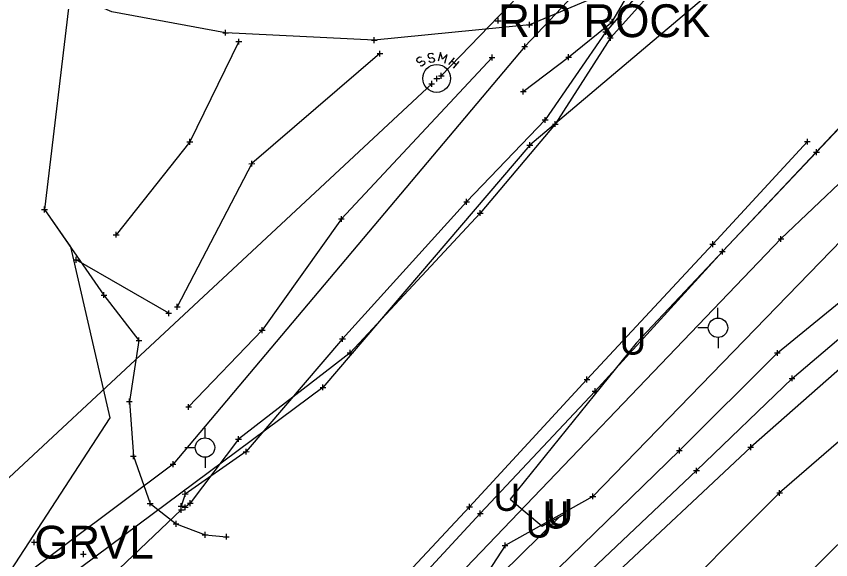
# Model space of a CAD drawing. Extents: x -1 to 1157254, y -1 to 2021979.
# Drawn here: x 1149359.7 to 1149538.4, y 2018913.3 to 2019032.4 of the extents above; entities that cross this region are included whole.
import ezdxf

# ---------------------------------------------------------------- set-up
doc = ezdxf.new("R2010")
doc.units = 0
for name, color, linetype in [('S_BUILDING_ANNOT', 7, 'Continuous'), ('S_CAL_CORNER_ANNOT', 7, 'Continuous'), ('S_CATCH_BASIN', 7, 'Continuous'), ('S_CONTOUR_ANNOT', 7, 'Continuous'), ('S_CONTOUR_MAJOR', 7, 'Continuous'), ('S_CONTOUR_MINOR', 7, 'Continuous'), ('S_CTL_TABLE', 7, 'Continuous'), ('S_DRIVEWAY_ANNOT', 7, 'Continuous'), ('S_DROP_INLET', 7, 'Continuous'), ('S_DROP_INLET_ANNOT', 7, 'Continuous'), ('S_DTM_PAVEMENT', 7, 'Continuous'), ('S_EDGE_BITUMINOUS_ANNOT', 7, 'Continuous'), ('S_EDGE_CONCRETE', 7, 'Continuous'), ('S_EDGE_PAVEMENT_ANNOT', 7, 'Continuous'), ('S_ENV_CONSTRAINT', 7, 'Continuous'), ('S_EXIST_ROW_ANNOT', 7, 'Continuous'), ('S_FENCE', 7, 'Continuous'), ('S_FLAG_POLE', 7, 'Continuous'), ('S_GAS_PUMP_ISLAND_ANNOT', 7, 'Continuous'), ('S_GATE', 7, 'Continuous')]:
    doc.layers.add(name, color=color, linetype=linetype)

msp = doc.modelspace()

# ---------------------------------------------------------------- linework, layer by layer
at = {"layer": 'S_BUILDING_ANNOT'}
for p, q in [((1149465.44, 2019030.78), (1149465.44, 2019032.05)), ((1149464.8, 2019031.42), (1149466.07, 2019031.42)), ((1149465.44, 2019031.42), (1149465.44, 2019031.42)), ((1149488.43, 2019028.95), (1149489.71, 2019028.95)), ((1149489.07, 2019028.31), (1149489.07, 2019029.58)), ((1149489.07, 2019028.95), (1149489.07, 2019028.95)), ((1149490.07, 2019027.02), (1149490.06, 2019028.29)), ((1149489.43, 2019027.65), (1149490.7, 2019027.66)), ((1149490.07, 2019027.66), (1149490.07, 2019027.66)), ((1149470.61, 2019025.77), (1149471.89, 2019025.78)), ((1149471.25, 2019025.14), (1149471.25, 2019026.41)), ((1149471.25, 2019025.78), (1149471.25, 2019025.78)), ((1149451.99, 2019018.1), (1149451.99, 2019019.37)), ((1149452.32, 2019019.35), (1149453.59, 2019019.35)), ((1149452.96, 2019018.71), (1149452.95, 2019019.98)), ((1149452.95, 2019019.35), (1149452.95, 2019019.35)), ((1149450.21, 2019017.6), (1149451.49, 2019017.6)), ((1149450.85, 2019016.96), (1149450.85, 2019018.23)), ((1149450.85, 2019017.6), (1149450.85, 2019017.6)), ((1149451.35, 2019018.73), (1149452.63, 2019018.74)), ((1149451.99, 2019018.73), (1149451.99, 2019018.73)), ((1149475.1, 2019009.67), (1149476.38, 2019009.67)), ((1149475.74, 2019009.04), (1149475.74, 2019010.31)), ((1149475.74, 2019009.67), (1149475.74, 2019009.67)), ((1149477.32, 2019008.76), (1149478.59, 2019008.76)), ((1149477.96, 2019008.13), (1149477.96, 2019009.4)), ((1149477.96, 2019008.76), (1149477.96, 2019008.76)), ((1149533.26, 2019004.27), (1149533.26, 2019005.55)), ((1149471.76, 2019004.16), (1149473.04, 2019004.16)), ((1149472.4, 2019003.52), (1149472.4, 2019004.79)), ((1149472.4, 2019004.16), (1149472.4, 2019004.16)), ((1149532.62, 2019004.91), (1149533.9, 2019004.91)), ((1149533.26, 2019004.91), (1149533.26, 2019004.91)), ((1149535.26, 2019001.98), (1149535.26, 2019003.25)), ((1149534.62, 2019002.62), (1149535.9, 2019002.62)), ((1149535.26, 2019002.62), (1149535.26, 2019002.62)), ((1149457.88, 2018991.72), (1149459.15, 2018991.72)), ((1149458.51, 2018991.09), (1149458.51, 2018992.36)), ((1149458.51, 2018991.72), (1149458.51, 2018991.72)), ((1149365.27, 2018990.03), (1149366.54, 2018990.03)), ((1149365.91, 2018989.4), (1149365.9, 2018990.67)), ((1149365.9, 2018990.03), (1149365.9, 2018990.03)), ((1149460.84, 2018989.26), (1149462.11, 2018989.26)), ((1149461.47, 2018988.63), (1149461.47, 2018989.9)), ((1149461.47, 2018989.26), (1149461.47, 2018989.26)), ((1149526.83, 2018983.58), (1149528.1, 2018983.58)), ((1149527.46, 2018982.94), (1149527.46, 2018984.21)), ((1149527.46, 2018983.58), (1149527.46, 2018983.58)), ((1149511.87, 2018982.43), (1149513.14, 2018982.43)), ((1149512.51, 2018981.79), (1149512.5, 2018983.06)), ((1149512.51, 2018982.43), (1149512.51, 2018982.43)), ((1149514, 2018980.81), (1149515.27, 2018980.81)), ((1149514.64, 2018980.17), (1149514.64, 2018981.44)), ((1149514.64, 2018980.81), (1149514.64, 2018980.81)), ((1149372.24, 2018979), (1149373.51, 2018979)), ((1149372.88, 2018978.37), (1149372.88, 2018979.64)), ((1149372.88, 2018979), (1149372.88, 2018979)), ((1149378.32, 2018971.27), (1149379.6, 2018971.28)), ((1149378.96, 2018970.64), (1149378.96, 2018971.91)), ((1149378.96, 2018971.28), (1149378.96, 2018971.28)), ((1149393.17, 2018966.66), (1149393.16, 2018967.93)), ((1149392.53, 2018967.3), (1149393.8, 2018967.3)), ((1149393.17, 2018967.3), (1149393.17, 2018967.3)), ((1149431.28, 2018961.02), (1149431.27, 2018962.29)), ((1149386, 2018961.34), (1149387.27, 2018961.34)), ((1149386, 2018961.33), (1149387.27, 2018961.34)), ((1149386.63, 2018960.7), (1149386.63, 2018961.97)), ((1149386.63, 2018961.33), (1149386.63, 2018961.33)), ((1149386.64, 2018960.71), (1149386.64, 2018961.98)), ((1149386.64, 2018961.34), (1149386.64, 2018961.34)), ((1149430.64, 2018961.65), (1149431.91, 2018961.65)), ((1149431.27, 2018961.65), (1149431.27, 2018961.65)), ((1149432.33, 2018958.61), (1149433.6, 2018958.61)), ((1149432.96, 2018957.97), (1149432.96, 2018959.24)), ((1149432.96, 2018958.61), (1149432.96, 2018958.61)), ((1149526.05, 2018958.59), (1149527.32, 2018958.59)), ((1149526.69, 2018957.95), (1149526.68, 2018959.22)), ((1149526.69, 2018958.59), (1149526.69, 2018958.59)), ((1149484.91, 2018952.13), (1149484.91, 2018953.4)), ((1149529.9, 2018952.37), (1149529.9, 2018953.65)), ((1149427, 2018950.4), (1149426.99, 2018951.67)), ((1149484.28, 2018952.77), (1149485.55, 2018952.77)), ((1149484.91, 2018952.77), (1149484.91, 2018952.77)), ((1149529.26, 2018953.01), (1149530.54, 2018953.01)), ((1149529.9, 2018953.01), (1149529.9, 2018953.01)), ((1149426.36, 2018951.03), (1149427.63, 2018951.04)), ((1149427, 2018951.04), (1149427, 2018951.04)), ((1149486.08, 2018950.24), (1149487.35, 2018950.24)), ((1149486.72, 2018949.6), (1149486.71, 2018950.87)), ((1149486.72, 2018950.24), (1149486.72, 2018950.24)), ((1149383.91, 2018947.96), (1149385.18, 2018947.96)), ((1149384.55, 2018947.32), (1149384.55, 2018948.59)), ((1149384.55, 2018947.96), (1149384.55, 2018947.96)), ((1149407.84, 2018939.71), (1149409.11, 2018939.72)), ((1149408.48, 2018939.08), (1149408.48, 2018940.35)), ((1149408.48, 2018939.72), (1149408.48, 2018939.72)), ((1149410.16, 2018936.32), (1149410.16, 2018937.59)), ((1149504.55, 2018937.2), (1149505.83, 2018937.2)), ((1149505.19, 2018936.56), (1149505.19, 2018937.83)), ((1149505.19, 2018937.2), (1149505.19, 2018937.2)), ((1149384.78, 2018935.98), (1149386.05, 2018935.98)), ((1149385.42, 2018935.34), (1149385.41, 2018936.61)), ((1149385.41, 2018935.98), (1149385.41, 2018935.98)), ((1149409.52, 2018936.95), (1149410.8, 2018936.96)), ((1149410.16, 2018936.96), (1149410.16, 2018936.96)), ((1149393.48, 2018934.21), (1149394.75, 2018934.21)), ((1149394.11, 2018933.57), (1149394.11, 2018934.85)), ((1149394.11, 2018934.21), (1149394.11, 2018934.21)), ((1149508.31, 2018932.79), (1149509.59, 2018932.79)), ((1149508.95, 2018932.16), (1149508.95, 2018933.43)), ((1149508.95, 2018932.79), (1149508.95, 2018932.79)), ((1149396.78, 2018927.03), (1149396.77, 2018928.3)), ((1149396.14, 2018927.66), (1149397.41, 2018927.67)), ((1149396.78, 2018927.66), (1149396.78, 2018927.66)), ((1149485.57, 2018927.15), (1149486.84, 2018927.15)), ((1149486.21, 2018926.51), (1149486.21, 2018927.78)), ((1149486.21, 2018927.15), (1149486.21, 2018927.15)), ((1149388.47, 2018925.62), (1149389.74, 2018925.62)), ((1149389.11, 2018924.98), (1149389.11, 2018926.26)), ((1149389.11, 2018925.62), (1149389.11, 2018925.62)), ((1149395.25, 2018925.02), (1149396.52, 2018925.02)), ((1149395.88, 2018924.38), (1149395.88, 2018925.66)), ((1149395.88, 2018925.02), (1149395.88, 2018925.02)), ((1149395.92, 2018923.54), (1149395.92, 2018924.81)), ((1149396.13, 2018924.74), (1149397.4, 2018924.75)), ((1149396.76, 2018924.11), (1149396.76, 2018925.38)), ((1149396.76, 2018924.74), (1149396.76, 2018924.74)), ((1149397.25, 2018925.65), (1149398.52, 2018925.66)), ((1149397.88, 2018925.02), (1149397.88, 2018926.29)), ((1149397.88, 2018925.65), (1149397.88, 2018925.65)), ((1149458.49, 2018924.84), (1149459.77, 2018924.84)), ((1149459.13, 2018924.21), (1149459.13, 2018925.48)), ((1149459.13, 2018924.84), (1149459.13, 2018924.84)), ((1149395.28, 2018924.18), (1149396.56, 2018924.18)), ((1149395.92, 2018924.18), (1149395.92, 2018924.18)), ((1149460.87, 2018923.38), (1149462.14, 2018923.38)), ((1149461.51, 2018922.75), (1149461.51, 2018924.02)), ((1149461.51, 2018923.38), (1149461.51, 2018923.38)), ((1149394.13, 2018921.13), (1149395.41, 2018921.14)), ((1149394.77, 2018920.5), (1149394.77, 2018921.77)), ((1149394.77, 2018921.14), (1149394.77, 2018921.14)), ((1149401.15, 2018918.07), (1149401.15, 2018919.34)), ((1149363.67, 2018916.46), (1149363.67, 2018917.73)), ((1149400.51, 2018918.7), (1149401.78, 2018918.7)), ((1149401.15, 2018918.7), (1149401.15, 2018918.7)), ((1149405.18, 2018918.31), (1149406.45, 2018918.31)), ((1149405.82, 2018917.67), (1149405.81, 2018918.95)), ((1149405.81, 2018918.31), (1149405.81, 2018918.31)), ((1149363.03, 2018917.1), (1149364.31, 2018917.1)), ((1149363.67, 2018917.1), (1149363.67, 2018917.1)), ((1149466.32, 2018916.39), (1149467.59, 2018916.4)), ((1149466.96, 2018915.76), (1149466.96, 2018917.03)), ((1149466.96, 2018916.4), (1149466.96, 2018916.4)), ((1149373.81, 2018914.49), (1149375.08, 2018914.49)), ((1149374.45, 2018913.85), (1149374.44, 2018915.13)), ((1149374.44, 2018914.49), (1149374.44, 2018914.49))]:
    msp.add_line(p, q, dxfattribs=at)
at = {"layer": 'S_CAL_CORNER_ANNOT'}
msp.add_lwpolyline([(1150682.05, 2019865.85), (1150601.54, 2019813.47), (1150510.58, 2019743.97), (1150405.28, 2019665.92), (1150310.69, 2019593.56), (1150188.92, 2019499.64), (1150039.45, 2019388.15), (1149962.15, 2019331.17), (1149944.63, 2019319.08), (1149774.15, 2019191.52), (1149712.73, 2019145.6), (1149665.81, 2019108.74), (1149605.46, 2019057.66), (1149527.46, 2018983.58), (1149450.12, 2018902.93), (1149278.32, 2018738.82), (1149257.2, 2018716.38), (1149237.23, 2018691.25), (1149165.09, 2018617.77), (1149125.26, 2018579.57), (1149069.5, 2018523.84), (1149012.03, 2018473.77), (1148938.88, 2018408.55)], dxfattribs=at)
at = {"layer": 'S_CATCH_BASIN'}
for p, q in [((1149513.66, 2018966.22), (1149513.66, 2018968.47)), ((1149511.57, 2018964.09), (1149509.24, 2018964.09)), ((1149513.74, 2018959.67), (1149513.74, 2018962)), ((1149401.13, 2018939.95), (1149401.13, 2018942.2)), ((1149399.03, 2018937.82), (1149396.71, 2018937.82)), ((1149401.2, 2018933.41), (1149401.2, 2018935.73))]:
    msp.add_line(p, q, dxfattribs=at)
for centre in [(1149513.66, 2018964.11), (1149401.13, 2018937.84)]:
    msp.add_circle(centre, 2.13, dxfattribs=at)
at = {"layer": 'S_CONTOUR_ANNOT'}
for points in [[(1149931.59, 2019393.98), (1149688.42, 2019230.92), (1149605.65, 2019167.39), (1149471.25, 2019025.78), (1149394.11, 2018934.21), (1149347.84, 2018899.68), (1149226.01, 2018779.47), (1149177.83, 2018729.86), (1148942.89, 2018495.75), (1148824.88, 2018414.4), (1148656.17, 2018321.62), (1148428.99, 2018204.95), (1148398.58, 2018185.48), (1148319.88, 2018123.12), (1148171.01, 2018007.64), (1148133.82, 2017978.13)], [(1149934.92, 2019374.11), (1149784.56, 2019258.12), (1149678.43, 2019178.13), (1149472.4, 2019004.16), (1149427, 2018951.04), (1149358.36, 2018900), (1149291.74, 2018823.41), (1149233.45, 2018767.69), (1149177.23, 2018710.91), (1149078.39, 2018616.37), (1148964.19, 2018499.8), (1148972, 2018491.15), (1148988.16, 2018467.17), (1149002.28, 2018452.45)]]:
    msp.add_lwpolyline(points, dxfattribs=at)
at = {"layer": 'S_CONTOUR_MINOR'}
for p, q in [((1149447.63, 2019023.07), (1149447.55, 2019022.68)), ((1149448.17, 2019023.45), (1149447.63, 2019023.07)), ((1149448.6, 2019023.38), (1149448.17, 2019023.45)), ((1149454.6, 2019021.83), (1149455.84, 2019023.3)), ((1149447.55, 2019022.68), (1149447.74, 2019022.41)), ((1149447.74, 2019022.41), (1149448.17, 2019022.29)), ((1149448.17, 2019022.29), (1149448.71, 2019022.64)), ((1149448.71, 2019021.48), (1149448.32, 2019021.56)), ((1149448.71, 2019022.64), (1149449.18, 2019022.56)), ((1149449.25, 2019021.87), (1149448.71, 2019021.48)), ((1149449.18, 2019022.56), (1149449.33, 2019022.29)), ((1149449.33, 2019022.29), (1149449.25, 2019021.87)), ((1149455.26, 2019022.6), (1149456.23, 2019021.79)), ((1149456.81, 2019022.49), (1149455.57, 2019021.01))]:
    msp.add_line(p, q, dxfattribs=at)
for points in [[(1149495.14, 2019063.02), (1149452.95, 2019019.35)], [(1149451.27, 2019024), (1149450.92, 2019024.27), (1149450.26, 2019024.19), (1149450.03, 2019023.84), (1149450.07, 2019023.53), (1149450.42, 2019023.22), (1149451.04, 2019023.34), (1149451.42, 2019023.03), (1149451.46, 2019022.72), (1149451.19, 2019022.33), (1149450.57, 2019022.25), (1149450.22, 2019022.52)], [(1149453.71, 2019022.14), (1149454.25, 2019024), (1149453.2, 2019022.99), (1149452.82, 2019024.42), (1149452.28, 2019022.56)], [(1149450.85, 2019017.6), (1149294.1, 2018871.71)]]:
    msp.add_lwpolyline(points, dxfattribs=at)
msp.add_circle((1149451.95, 2019018.77), 3.05, dxfattribs=at)
at = {"layer": 'S_CTL_TABLE'}
for p, q in [((1149490.47, 2019030.54), (1149490.47, 2019031.81)), ((1149471.7, 2019030.54), (1149472.97, 2019030.55)), ((1149472.34, 2019029.91), (1149472.33, 2019031.18)), ((1149472.33, 2019030.55), (1149472.33, 2019030.55)), ((1149489.84, 2019031.17), (1149491.11, 2019031.18)), ((1149490.47, 2019031.18), (1149490.47, 2019031.18)), ((1149405, 2019028.8), (1149406.27, 2019028.8)), ((1149405.64, 2019028.17), (1149405.63, 2019029.44)), ((1149405.64, 2019028.8), (1149405.64, 2019028.8)), ((1149407.91, 2019026.84), (1149409.18, 2019026.84)), ((1149408.55, 2019026.2), (1149408.54, 2019027.47)), ((1149408.55, 2019026.84), (1149408.55, 2019026.84)), ((1149437.62, 2019027.17), (1149438.89, 2019027.17)), ((1149438.25, 2019026.53), (1149438.25, 2019027.81)), ((1149438.25, 2019027.17), (1149438.25, 2019027.17)), ((1149439.5, 2019023.57), (1149439.5, 2019024.84)), ((1149438.86, 2019024.21), (1149440.14, 2019024.21)), ((1149439.5, 2019024.21), (1149439.5, 2019024.21)), ((1149463.47, 2019023.36), (1149464.74, 2019023.36)), ((1149464.11, 2019022.72), (1149464.1, 2019024)), ((1149464.1, 2019023.36), (1149464.1, 2019023.36)), ((1149480.26, 2019023.42), (1149481.53, 2019023.42)), ((1149480.9, 2019022.79), (1149480.9, 2019024.06)), ((1149480.9, 2019023.42), (1149480.9, 2019023.42)), ((1149470.31, 2019015.88), (1149471.58, 2019015.88)), ((1149470.95, 2019015.24), (1149470.95, 2019016.51)), ((1149470.95, 2019015.88), (1149470.95, 2019015.88)), ((1149397.78, 2019004.23), (1149397.78, 2019005.5)), ((1149397.14, 2019004.86), (1149398.42, 2019004.87)), ((1149397.78, 2019004.87), (1149397.78, 2019004.87)), ((1149410.77, 2019000.08), (1149412.05, 2019000.09)), ((1149411.41, 2018999.45), (1149411.41, 2019000.72)), ((1149411.41, 2019000.09), (1149411.41, 2019000.09)), ((1149430.41, 2018987.97), (1149431.68, 2018987.98)), ((1149431.05, 2018987.34), (1149431.05, 2018988.61)), ((1149431.05, 2018987.97), (1149431.05, 2018987.97)), ((1149380.99, 2018984.5), (1149382.26, 2018984.5)), ((1149381.62, 2018983.87), (1149381.62, 2018985.14)), ((1149381.62, 2018984.5), (1149381.62, 2018984.5)), ((1149395.05, 2018968.07), (1149395.04, 2018969.35)), ((1149394.41, 2018968.71), (1149395.68, 2018968.71)), ((1149395.04, 2018968.71), (1149395.04, 2018968.71)), ((1149413.67, 2018962.94), (1149413.66, 2018964.21)), ((1149413.03, 2018963.58), (1149414.3, 2018963.58)), ((1149413.66, 2018963.58), (1149413.66, 2018963.58)), ((1149396.89, 2018946.75), (1149398.16, 2018946.75)), ((1149397.53, 2018946.11), (1149397.52, 2018947.38)), ((1149397.52, 2018946.75), (1149397.52, 2018946.75)), ((1149520.19, 2018937.94), (1149521.47, 2018937.94)), ((1149520.83, 2018937.3), (1149520.83, 2018938.58)), ((1149520.83, 2018937.94), (1149520.83, 2018937.94)), ((1149527.18, 2018927.26), (1149527.17, 2018928.53)), ((1149526.54, 2018927.9), (1149527.81, 2018927.9)), ((1149527.17, 2018927.9), (1149527.17, 2018927.9))]:
    msp.add_line(p, q, dxfattribs=at)
at = {"layer": 'S_DRIVEWAY_ANNOT'}
for points in [[(1149497.48, 2019039.56), (1149496.43, 2019037.66), (1149489.07, 2019028.95), (1149475.74, 2019009.67), (1149458.51, 2018991.72), (1149431.27, 2018961.65), (1149410.16, 2018936.96), (1149396.78, 2018927.66), (1149395.88, 2018925.02)], [(1149499.26, 2019039.26), (1149498.04, 2019036.62), (1149490.07, 2019027.66), (1149477.96, 2019008.76), (1149461.47, 2018989.26), (1149432.96, 2018958.61), (1149408.48, 2018939.72), (1149397.88, 2018925.65), (1149396.76, 2018924.74)], [(1149376.61, 2018808.08), (1149378.14, 2018810.98), (1149389.01, 2018823.67), (1149409.46, 2018847.56), (1149440.18, 2018874.39), (1149475.97, 2018908.75), (1149505.19, 2018937.2), (1149526.69, 2018958.59), (1149556.52, 2018982.92), (1149580.72, 2019006.3), (1149603.46, 2019020.75), (1149621.36, 2019031.87)], [(1149376.44, 2018806.04), (1149380.49, 2018808.15), (1149394.25, 2018816.7), (1149415.4, 2018840.88), (1149444.35, 2018868.67), (1149479.15, 2018904.69), (1149508.95, 2018932.79), (1149529.9, 2018953.01), (1149559.1, 2018977.73), (1149584.9, 2019000.96), (1149605.2, 2019016.88), (1149625.32, 2019028.84)]]:
    msp.add_lwpolyline(points, dxfattribs=at)
at = {"layer": 'S_DROP_INLET'}
for points in [[(1149587.97, 2019053.68), (1149551.81, 2019020.22), (1149495.72, 2018960.76), (1149468.06, 2018926.51), (1149475.12, 2018920.64), (1149479.69, 2018923.12)], [(1149478.88, 2018922.64), (1149385.84, 2018831.36), (1149330.57, 2018775.16), (1149250.6, 2018696.8), (1149231.5, 2018678.75), (1149169.67, 2018614.3), (1149128.45, 2018577.04), (1149075.89, 2018529.44), (1149016.28, 2018476.33), (1148941.34, 2018408.7), (1148861.11, 2018354.7), (1148778.49, 2018311.96), (1148755.86, 2018297.95), (1148577.39, 2018201.52), (1148460.64, 2018136.54), (1148334.57, 2018041.74), (1148195.53, 2017935.77), (1148138.82, 2017892.99)]]:
    msp.add_lwpolyline(points, dxfattribs=at)
at = {"layer": 'S_DROP_INLET_ANNOT'}
msp.add_lwpolyline([(1149395.92, 2018924.18), (1149362.83, 2018892.8)], dxfattribs=at)
at = {"layer": 'S_DTM_PAVEMENT'}
msp.add_lwpolyline([(1149393.17, 2018967.3), (1149372.88, 2018979)], dxfattribs=at)
at = {"layer": 'S_EDGE_BITUMINOUS_ANNOT'}
for points in [[(1149470.95, 2019015.88), (1149480.9, 2019023.42), (1149490.47, 2019031.18), (1149495.83, 2019040.44), (1149472.33, 2019030.55), (1149438.25, 2019027.17), (1149405.64, 2019028.8), (1149380.72, 2019033.36), (1149343.09, 2019049.73), (1149326.07, 2019062), (1149301.59, 2019079.71), (1149283.88, 2019097.02), (1149282.36, 2019113.17), (1149265.52, 2019117.42)], [(1149408.55, 2019026.84), (1149397.78, 2019004.87), (1149381.62, 2018984.5)], [(1149439.5, 2019024.21), (1149411.41, 2019000.09), (1149395.04, 2018968.71)], [(1149464.1, 2019023.36), (1149431.05, 2018987.97), (1149413.66, 2018963.58), (1149397.52, 2018946.75)], [(1149660.03, 2018976.65), (1149631.99, 2018985.75), (1149603.08, 2018981.73), (1149578.25, 2018978.73), (1149548.87, 2018962.54), (1149520.83, 2018937.94), (1149489.35, 2018908.4), (1149463.06, 2018881.32), (1149437.76, 2018856.18), (1149412.61, 2018831.09), (1149389.75, 2018805.71)], [(1149658.16, 2018967.63), (1149629.1, 2018977.29), (1149605.68, 2018973.28), (1149580.28, 2018967.82), (1149554.15, 2018951.27), (1149527.17, 2018927.9), (1149498.99, 2018899.71), (1149468.02, 2018871.41), (1149443.75, 2018849.24), (1149417.05, 2018823.84), (1149394.92, 2018799.71)]]:
    msp.add_lwpolyline(points, dxfattribs=at)
at = {"layer": 'S_EDGE_CONCRETE'}
msp.add_lwpolyline([(1149391.91, 2018853), (1149412.71, 2018874.99), (1149434.25, 2018898.25), (1149459.13, 2018924.84), (1149484.91, 2018952.77), (1149512.51, 2018982.43), (1149533.26, 2019004.91)], dxfattribs=at)
at = {"layer": 'S_EDGE_PAVEMENT_ANNOT'}
msp.add_lwpolyline([(1149365.9, 2018990.03), (1149378.96, 2018971.28), (1149386.64, 2018961.34)], dxfattribs=at)
at = {"layer": 'S_ENV_CONSTRAINT'}
msp.add_lwpolyline([(1149386.63, 2018961.33), (1149384.55, 2018947.96), (1149385.41, 2018935.98), (1149389.11, 2018925.62), (1149394.77, 2018921.14), (1149401.15, 2018918.7), (1149405.81, 2018918.31)], dxfattribs=at)
at = {"layer": 'S_EXIST_ROW_ANNOT'}
msp.add_lwpolyline([(1149687.95, 2018942.37), (1149653.9, 2018955.87), (1149603.23, 2018961.52), (1149562.49, 2018938.88), (1149526.26, 2018903.04), (1149498.23, 2018881.1), (1149458.63, 2018846.1), (1149419.57, 2018813.34), (1149387.83, 2018776.41), (1149372.07, 2018764.27)], dxfattribs=at)
at = {"layer": 'S_FENCE'}
msp.add_lwpolyline([(1149562.21, 2019005.4), (1149486.21, 2018927.15), (1149466.96, 2018916.4), (1149448.15, 2018887.45), (1149385.38, 2018826.9), (1149357.5, 2018803.66), (1149334.17, 2018772.97), (1149278.68, 2018714.02), (1149266.21, 2018707.99), (1149250.6, 2018696.75), (1149241.46, 2018677.2), (1149179.13, 2018611.74), (1149130.37, 2018567.15), (1149080.16, 2018520.92), (1149020.19, 2018471.53), (1148946.08, 2018397.31), (1148842.28, 2018340.54), (1148783.26, 2018310.71), (1148755.06, 2018299.13), (1148580.09, 2018196.31), (1148464.77, 2018128.06), (1148357.29, 2018049.22), (1148182.05, 2017918.06), (1148146.03, 2017882.74)], dxfattribs=at)
at = {"layer": 'S_FLAG_POLE'}
msp.add_lwpolyline([(1149394.42, 2018850.82), (1149415.26, 2018873.51), (1149435.66, 2018895.49), (1149461.51, 2018923.38), (1149486.72, 2018950.24), (1149514.64, 2018980.81), (1149535.26, 2019002.62), (1149558.12, 2019026.71)], dxfattribs=at)
at = {"layer": 'S_GAS_PUMP_ISLAND_ANNOT'}
msp.add_lwpolyline([(1149353.22, 2019045.32), (1149362.38, 2019041.34), (1149371.55, 2019037.35), (1149365.9, 2018990.03), (1149371.62, 2018981.83), (1149380.22, 2018944.38), (1149353.45, 2018903.35)], dxfattribs=at)

# ---------------------------------------------------------------- texts
at = {"layer": 'S_CONTOUR_MAJOR'}
for p in [(1149492.09, 2018958.22), (1149464.43, 2018923.97), (1149476.06, 2018920.58), (1149475.25, 2018920.09), (1149471.49, 2018918.09)]:
    msp.add_text('U', height=6, dxfattribs=at).set_placement(p)
at = {"layer": 'S_GATE'}
for s, p in [('RIP ROCK', (1149465.44, 2019027.82)), ('GRVL', (1149363.67, 2018913.5))]:
    msp.add_text(s, height=7.2, dxfattribs=at).set_placement(p)

doc.saveas('drawing.dxf')
